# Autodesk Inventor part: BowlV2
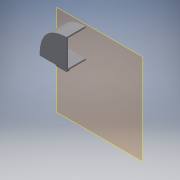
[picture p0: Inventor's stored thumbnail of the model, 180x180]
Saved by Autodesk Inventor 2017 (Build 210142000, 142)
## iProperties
Created: 2017-05
Part Number: BowlV2
Material: Generic
Document SubType Name: Modeling
Designer: 1460374
Density: 1 g/cm^3
Appearance: Default
Author: 1460374
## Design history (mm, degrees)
workplane "Work Plane1"
sketch "Sketch1"
  geometry: L1 (3.468, 119.669)-(38.439, 119.669); L2 (35.523, 122.585)-(-16.678, 122.585); L3 (35.523, 179.902)-(38.439, 179.902); L4 (35.523, 122.585)-(38.439, 122.585); L5 (38.439, 119.669)-(38.439, 122.585); L6 (38.439, 179.902)-(38.439, 182.959); L7 (-19.593, 119.669)-(-19.593, 82.666); L8 (-19.593, 82.666)-(3.468, 82.666); L9 (3.468, 82.666)-(3.468, 119.669); L10 (3.468, 119.669)-(-19.593, 119.669); 2 further points
  constraints: 20 end point, 8 perpendicular, 2 horizontal, 1 vertical, 6 other
extrude "Extrusion1" new body sketch "Sketch1" distance "d0" = 38.1; taper "d1" = 0 deg
extrude "Extrusion2" join sketch "Sketch1" distance "d2" = 3.175; taper "d3" = 0 deg
sketch "Sketch2"
  geometry: L1 (38.439, 182.959)-(38.439, 119.669); L2 (-19.593, 119.669)-(38.439, 119.669) reference; L3 (38.439, 119.669)-(-19.593, 119.669); 1 further point
  constraints: 4 end point, 1 collinear, 1 vertical, 1 other
extrude "Extrusion3" join sketch "Sketch2" distance "d4" = 3.175; taper "d5" = 0 deg
body "Solid1"
